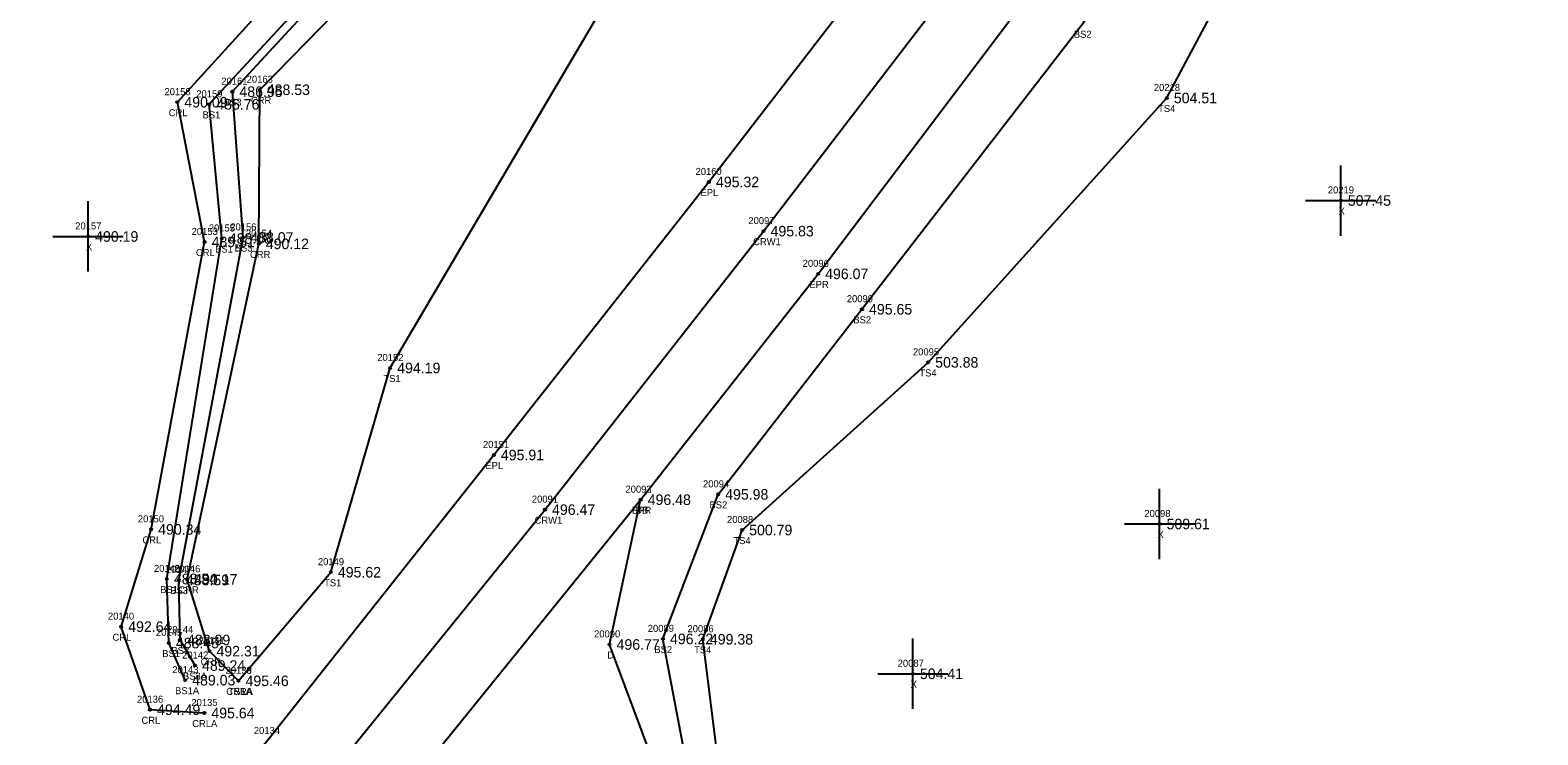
# Model space of a CAD drawing. Extents: x 1649406 to 1650436, y 896752 to 898178.
# Drawn here: x 1649581.2 to 1649795.4, y 896995.9 to 897096.1 of the extents above; entities that cross this region are included whole.
import ezdxf

# ---------------------------------------------------------------- set-up
doc = ezdxf.new("R2010")
doc.units = 0
for name, color, linetype in [('RD_DTM_BkLn1', 7, 'Continuous'), ('RD_DTM_BkLn2', 7, 'Continuous'), ('RD_DTM_BkLn_txCode', 7, 'Continuous'), ('RD_EX_Driveway', 7, 'Continuous'), ('RD_EX_Driveway_txCode', 7, 'Continuous'), ('RD_EX_H2O', 7, 'Continuous'), ('RD_EX_H2O_txCode', 7, 'Continuous'), ('RD_EX_Misc', 7, 'Continuous'), ('RD_EX_Misc_txCode', 7, 'Continuous'), ('RD_EX_Road', 7, 'Continuous'), ('RD_EX_Road_txCode', 7, 'Continuous'), ('RD_EX_TX_Driveway_ELEV', 7, 'Continuous'), ('RD_EX_TX_H2O_ELEV', 7, 'Continuous'), ('RD_EX_TX_Misc_ELEV', 7, 'Continuous'), ('RD_EX_TX_Road_ELEV', 7, 'Continuous'), ('RD_HC_Survey_ELEV', 7, 'Continuous'), ('RD_HC_Survey_txCode', 7, 'Continuous'), ('RD_SMD_Locator', 7, 'Continuous')]:
    doc.layers.add(name, color=color, linetype=linetype)

msp = doc.modelspace()

# ---------------------------------------------------------------- linework, layer by layer
at = {"layer": 'RD_DTM_BkLn1'}
msp.add_lwpolyline([(1649466.79, 896799.14), (1649494.97, 896834.25), (1649557.53, 896909.97), (1649590.88, 896950.41), (1649622.36, 896988.16), (1649622.36, 896988.48), (1649654.33, 897027.92), (1649685.38, 897067.52), (1649715.96, 897107.48), (1649743.64, 897146.32), (1649771.01, 897187.23), (1649797.64, 897230.08), (1649820.89, 897273.98), (1649842.91, 897321.22), (1649862.74, 897368.05), (1649877.08, 897408.66)], dxfattribs=at)
at = {"layer": 'RD_DTM_BkLn2'}
for points in [[(1649604.6, 897005.75), (1649602.47, 897009.39), (1649602.3, 897017.91), (1649611.46, 897066.62), (1649609.91, 897087.35), (1649647.02, 897127.55), (1649667.48, 897155.95), (1649673.52, 897172.2), (1649701.06, 897200.6), (1649725.89, 897215.14), (1649740.6, 897244.69), (1649756.42, 897243.48), (1649789.18, 897306.38), (1649812.44, 897341.7), (1649825.72, 897367.05), (1649832.43, 897399.23), (1649835.49, 897415.79), (1649852.17, 897423.43), (1649870.24, 897429.91)], [(1649603.2, 897003.67), (1649600.88, 897008.96), (1649600.6, 897018.07), (1649608.4, 897066.47), (1649606.62, 897085.55), (1649645.06, 897127.13), (1649665.04, 897155.81), (1649672.23, 897173.72), (1649699.83, 897202.17), (1649724.61, 897216.67), (1649739.3, 897246.84), (1649755.02, 897245.48), (1649787.66, 897308.84)], [(1649689.03, 896955.15), (1649675.54, 896986.1), (1649671.09, 897009.54), (1649678.93, 897030.09), (1649699.37, 897056.41), (1649730.7, 897097.01), (1649758.94, 897137.57), (1649785.6, 897178.21), (1649814.8, 897219.5), (1649846.42, 897264.34)], [(1649692.17, 896958.45), (1649679.46, 896987.93), (1649676.76, 897009.49), (1649682.34, 897025.02), (1649708.77, 897048.86), (1649742.68, 897086.45), (1649767.3, 897132.79), (1649789.94, 897176.61), (1649819.17, 897217.64), (1649850.28, 897262.86)], [(1649610.78, 897003.58), (1649623.9, 897019.02), (1649632.33, 897048.06), (1649665.12, 897103.78), (1649684.52, 897130.04), (1649709.45, 897167.77)]]:
    msp.add_lwpolyline(points, dxfattribs=at)
at = {"layer": 'RD_EX_Driveway'}
msp.add_lwpolyline([(1649687.07, 896952.98), (1649672.35, 896985.05), (1649663.5, 897008.75), (1649667.92, 897029.33)], dxfattribs=at)
at = {"layer": 'RD_EX_H2O'}
for points in [[(1649610.78, 897003.58), (1649606.65, 897007.8), (1649603.49, 897018.01), (1649613.66, 897065.71), (1649613.8, 897087.62), (1649648.77, 897123.4), (1649673.15, 897145.36), (1649677.84, 897170.04), (1649704.36, 897195), (1649732.98, 897211.32), (1649741.05, 897244.13), (1649760.18, 897240.39), (1649790.48, 897304.8), (1649814.66, 897340.98), (1649827.92, 897366.62), (1649835.63, 897392.05), (1649839.2, 897413.36), (1649851.88, 897417.91), (1649868.27, 897424.7)], [(1649605.92, 896999), (1649598.21, 896999.47), (1649594.11, 897011.28), (1649598.36, 897025.11), (1649605.96, 897065.98), (1649602.09, 897085.85), (1649642.84, 897130.64), (1649663.84, 897157.19), (1649669.86, 897175.88), (1649698.27, 897205.65), (1649723.06, 897216.5), (1649737.55, 897250.43), (1649753.58, 897247.01), (1649784.63, 897314.89)]]:
    msp.add_lwpolyline(points, dxfattribs=at)
at = {"layer": 'RD_EX_Misc'}
for p, q in [((1649767.4, 897066.87), (1649767.4, 897076.87)), ((1649589.41, 897061.76), (1649589.41, 897071.76)), ((1649762.4, 897071.87), (1649772.4, 897071.87)), ((1649584.41, 897066.76), (1649594.41, 897066.76)), ((1649741.65, 897020.88), (1649741.65, 897030.88)), ((1649736.65, 897025.88), (1649746.65, 897025.88)), ((1649706.6, 896999.58), (1649706.6, 897009.58)), ((1649701.6, 897004.58), (1649711.6, 897004.58))]:
    msp.add_line(p, q, dxfattribs=at)
at = {"layer": 'RD_EX_Road'}
for points in [[(1649459.38, 896805.71), (1649486.55, 896839.62), (1649513.65, 896873.34), (1649538.22, 896902.56), (1649549.43, 896916.62), (1649583.1, 896957.27), (1649614.8, 896995.02), (1649647.06, 897035.69), (1649677.62, 897074.51), (1649708.33, 897114.44), (1649735.5, 897151.61), (1649762.11, 897192.19), (1649788.21, 897235.29), (1649812.17, 897279.73), (1649834.32, 897326.54), (1649852.94, 897371.82), (1649867.51, 897411.96)], [(1649474.75, 896792.65), (1649502.78, 896827.35), (1649565.2, 896903.92), (1649598.28, 896943.71), (1649629.8, 896982.26), (1649667.92, 897029.33), (1649693.13, 897061.44), (1649723.58, 897101.84), (1649752.37, 897141.09), (1649779.72, 897182.3), (1649806.12, 897225.84), (1649830.13, 897270.79), (1649852.39, 897317.43), (1649871.98, 897364.35), (1649886.55, 897406.09)]]:
    msp.add_lwpolyline(points, dxfattribs=at)
at = {"layer": 'RD_SMD_Locator'}
for centre in [(1649609.91, 897087.35), (1649613.8, 897087.62), (1649742.68, 897086.45), (1649602.09, 897085.85), (1649606.62, 897085.55), (1649677.62, 897074.51), (1649767.4, 897071.87), (1649589.41, 897066.76), (1649611.46, 897066.62), (1649685.38, 897067.52), (1649605.96, 897065.98), (1649608.4, 897066.47), (1649613.66, 897065.71), (1649693.13, 897061.44), (1649699.37, 897056.41), (1649632.33, 897048.06), (1649708.77, 897048.86), (1649647.06, 897035.69), (1649667.92, 897029.33), (1649667.92, 897029.33), (1649678.93, 897030.09), (1649654.33, 897027.92), (1649598.36, 897025.11), (1649682.34, 897025.02), (1649741.65, 897025.88), (1649600.6, 897018.07), (1649602.3, 897017.91), (1649603.49, 897018.01), (1649623.9, 897019.02), (1649594.11, 897011.28), (1649600.88, 897008.96), (1649602.47, 897009.39), (1649671.09, 897009.54), (1649676.76, 897009.49), (1649606.65, 897007.8), (1649663.5, 897008.75), (1649604.6, 897005.75), (1649706.6, 897004.58), (1649603.2, 897003.67), (1649610.78, 897003.58), (1649610.78, 897003.58), (1649598.21, 896999.47), (1649605.92, 896999)]:
    msp.add_circle(centre, 0.15, dxfattribs=at)

# ---------------------------------------------------------------- texts
at = {"layer": 'RD_DTM_BkLn_txCode'}
for s, p in [('BS2', (1649729.47, 897095.01)), ('20161', (1649608.34, 897088.35)), ('20218', (1649740.84, 897087.45)), ('20159', (1649604.78, 897086.55)), ('BS3', (1649608.68, 897085.35)), ('BS1', (1649605.67, 897083.55)), ('TS4', (1649741.44, 897084.45)), ('20155', (1649606.56, 897067.47)), ('20156', (1649609.61, 897067.62)), ('BS1', (1649607.45, 897064.47)), ('BS3', (1649610.24, 897064.62)), ('20099', (1649697.21, 897057.41)), ('BS2', (1649698.14, 897054.41)), ('20152', (1649630.5, 897049.06)), ('20095', (1649706.61, 897049.86)), ('TS4', (1649707.52, 897046.86)), ('TS1', (1649631.37, 897046.06)), ('20094', (1649676.78, 897031.09)), ('BS2', (1649677.7, 897028.09)), ('20088', (1649680.19, 897026.02)), ('TS4', (1649681.1, 897023.02)), ('20148', (1649598.76, 897019.07)), ('20147', (1649600.47, 897018.91)), ('20149', (1649622.06, 897020.02)), ('TS1', (1649622.94, 897017.02)), ('BS1', (1649599.65, 897016.07)), ('BS3', (1649601.07, 897015.91)), ('20144', (1649600.64, 897010.39)), ('20089', (1649668.93, 897010.54)), ('20086', (1649674.57, 897010.49)), ('20145', (1649599.05, 897009.96)), ('BS1', (1649599.94, 897006.96)), ('BS3', (1649601.24, 897007.39)), ('20142', (1649602.77, 897006.75)), ('BS2', (1649669.86, 897007.54)), ('TS4', (1649675.51, 897007.49)), ('20143', (1649601.37, 897004.67)), ('BS3A', (1649602.88, 897003.75)), ('20138', (1649608.95, 897004.58)), ('BS1A', (1649601.77, 897001.67)), ('TS1A', (1649609.34, 897001.58))]:
    msp.add_text(s, height=1, dxfattribs=at).set_placement(p)
at = {"layer": 'RD_EX_Driveway_txCode'}
for s, p in [('20092', (1649665.76, 897030.33)), ('DB', (1649667.14, 897027.33)), ('20090', (1649661.3, 897009.75)), ('D', (1649663.19, 897006.75))]:
    msp.add_text(s, height=1, dxfattribs=at).set_placement(p)
at = {"layer": 'RD_EX_H2O_txCode'}
for s, p in [('20163', (1649611.94, 897088.62)), ('20158', (1649600.26, 897086.85)), ('CRR', (1649612.54, 897085.62)), ('CRL', (1649600.86, 897083.85)), ('20153', (1649604.12, 897066.98)), ('20154', (1649611.83, 897066.71)), ('CRL', (1649604.73, 897063.98)), ('CRR', (1649612.41, 897063.71)), ('20150', (1649596.48, 897026.11)), ('CRL', (1649597.13, 897023.11)), ('20146', (1649601.63, 897019.01)), ('CRR', (1649602.24, 897016.01)), ('20140', (1649592.23, 897012.28)), ('CRL', (1649592.88, 897009.28)), ('20141', (1649605.1, 897008.8)), ('CRR', (1649605.4, 897005.8)), ('20139', (1649608.95, 897004.58)), ('CRRA', (1649609.04, 897001.58)), ('20136', (1649596.36, 897000.47)), ('20135', (1649604.08, 897000)), ('CRL', (1649596.99, 896997.47)), ('CRLA', (1649604.2, 896997))]:
    msp.add_text(s, height=1, dxfattribs=at).set_placement(p)
at = {"layer": 'RD_EX_Misc_txCode'}
for s, p in [('20219', (1649765.56, 897072.87)), ('X', (1649767.08, 897069.87)), ('20157', (1649587.58, 897067.76)), ('X', (1649589.1, 897064.76)), ('20098', (1649739.49, 897026.88)), ('X', (1649741.34, 897023.88)), ('20087', (1649704.44, 897005.58)), ('X', (1649706.28, 897002.58))]:
    msp.add_text(s, height=1, dxfattribs=at).set_placement(p)
at = {"layer": 'RD_EX_Road_txCode'}
for s, p in [('20160', (1649675.72, 897075.51)), ('EPL', (1649676.42, 897072.51)), ('20096', (1649690.94, 897062.44)), ('EPR', (1649691.9, 897059.44)), ('20151', (1649645.51, 897036.69)), ('EPL', (1649645.86, 897033.69)), ('20093', (1649665.76, 897030.33)), ('EPR', (1649666.69, 897027.33)), ('20134', (1649612.96, 896996.02))]:
    msp.add_text(s, height=1, dxfattribs=at).set_placement(p)
at = {"layer": 'RD_EX_TX_Driveway_ELEV'}
for s, p in [('496.48', (1649668.92, 897028.58)), ('496.77', (1649664.5, 897008))]:
    msp.add_text(s, height=1.5, dxfattribs=at).set_placement(p)
at = {"layer": 'RD_EX_TX_H2O_ELEV'}
for s, p in [('488.53', (1649614.8, 897086.87)), ('490.09', (1649603.09, 897085.1)), ('489.51', (1649606.96, 897065.23)), ('490.12', (1649614.66, 897064.96)), ('490.34', (1649599.36, 897024.36)), ('490.17', (1649604.49, 897017.26)), ('492.64', (1649595.11, 897010.53)), ('492.31', (1649607.65, 897007.05)), ('495.46', (1649611.78, 897002.83)), ('494.49', (1649599.21, 896998.72)), ('495.64', (1649606.92, 896998.25))]:
    msp.add_text(s, height=1.5, dxfattribs=at).set_placement(p)
at = {"layer": 'RD_EX_TX_Misc_ELEV'}
for s, p in [('486.76', (1649607.62, 897084.8)), ('486.95', (1649610.91, 897086.6)), ('504.51', (1649743.68, 897085.7)), ('507.45', (1649768.4, 897071.12)), ('490.19', (1649590.41, 897066.01)), ('488.08', (1649609.4, 897065.72)), ('488.07', (1649612.46, 897065.87)), ('495.65', (1649700.37, 897055.66)), ('503.88', (1649709.77, 897048.11)), ('494.19', (1649633.33, 897047.31)), ('495.98', (1649679.93, 897029.34)), ('509.61', (1649742.65, 897025.13)), ('500.79', (1649683.34, 897024.27)), ('495.62', (1649624.9, 897018.27)), ('488.54', (1649601.6, 897017.32)), ('488.59', (1649603.3, 897017.16)), ('488.45', (1649601.88, 897008.21)), ('488.99', (1649603.47, 897008.64)), ('496.22', (1649672.09, 897008.79)), ('499.38', (1649677.76, 897008.74)), ('489.24', (1649605.6, 897005)), ('504.41', (1649707.6, 897003.83)), ('489.03', (1649604.2, 897002.92)), ('495.46', (1649611.78, 897002.83))]:
    msp.add_text(s, height=1.5, dxfattribs=at).set_placement(p)
at = {"layer": 'RD_EX_TX_Road_ELEV'}
for s, p in [('495.32', (1649678.62, 897073.76)), ('496.07', (1649694.13, 897060.69)), ('495.91', (1649648.06, 897034.94)), ('496.48', (1649668.92, 897028.58))]:
    msp.add_text(s, height=1.5, dxfattribs=at).set_placement(p)
at = {"layer": 'RD_HC_Survey_ELEV'}
for s, p in [('495.83', (1649686.38, 897066.77)), ('496.47', (1649655.33, 897027.17))]:
    msp.add_text(s, height=1.5, dxfattribs=at).set_placement(p)
at = {"layer": 'RD_HC_Survey_txCode'}
for s, p in [('20097', (1649683.22, 897068.52)), ('CRW1', (1649683.9, 897065.52)), ('20091', (1649652.46, 897028.92)), ('CRW1', (1649652.85, 897025.92))]:
    msp.add_text(s, height=1, dxfattribs=at).set_placement(p)

doc.saveas('drawing.dxf')
